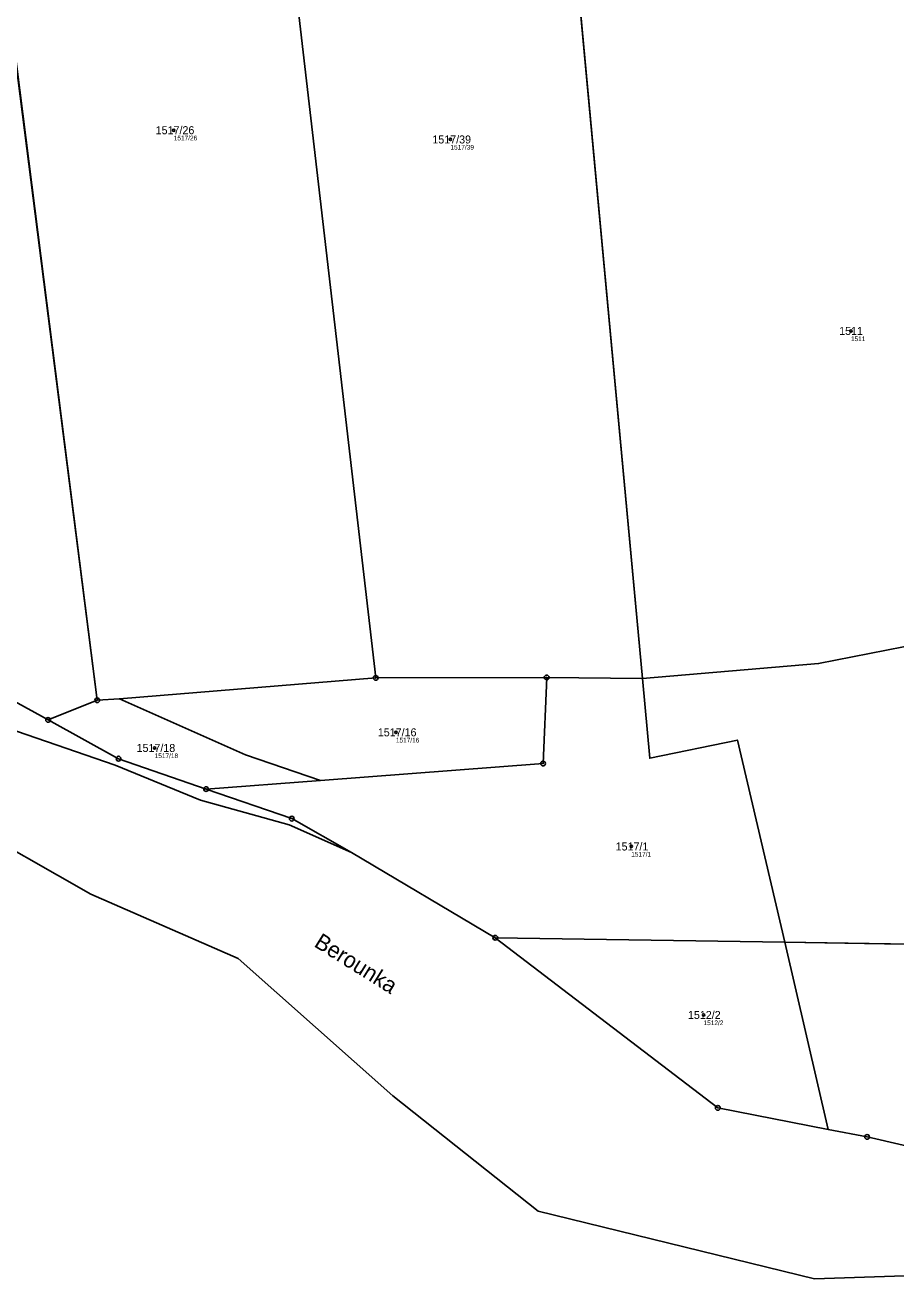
# Model space of a CAD drawing. Extents: x -751550 to -746116, y -1055108 to -1050700.
# Drawn here: x -749512.3 to -749327.2, y -1055107.6 to -1054841.3 of the extents above; entities that cross this region are included whole.
import ezdxf

# ---------------------------------------------------------------- set-up
doc = ezdxf.new("R2010")
doc.units = 0
for name, color, linetype in [('Definiční body', 7, 'Continuous'), ('Hranice parcel', 7, 'Continuous'), ('Parcelní čísla', 7, 'Continuous'), ('Polygon ku', 7, 'Continuous'), ('Polygon parcely', 7, 'Continuous'), ('Pop  PČ popisy', 7, 'Continuous'), ('Značky bodu BP', 7, 'Continuous')]:
    doc.layers.add(name, color=color, linetype=linetype)

msp = doc.modelspace()

# ---------------------------------------------------------------- linework, layer by layer
at = {"layer": 'Definiční body'}
for centre in [(-749480.66, -1054863.59), (-749421.87, -1054865.55), (-749336.76, -1054906.23), (-749433.46, -1054991.49), (-749484.72, -1054994.81), (-749383.45, -1055015.74), (-749368.09, -1055051.53)]:
    msp.add_circle(centre, 0.25, dxfattribs=at)
at = {"layer": 'Hranice parcel'}
for p, q in [((-749396.48, -1054814.13), (-749381.09, -1054980.09)), ((-749496.91, -1054984.67), (-749517.86, -1054820.37)), ((-749437.74, -1054979.93), (-749492.19, -1054984.36)), ((-749437.74, -1054979.93), (-749401.42, -1054979.83)), ((-749381.09, -1054980.09), (-749401.42, -1054979.83)), ((-749507.37, -1054988.85), (-749496.91, -1054984.67)), ((-749492.19, -1054984.36), (-749496.91, -1054984.67)), ((-749449.5, -1055001.7), (-749473.8, -1055003.54)), ((-749442.86, -1055016.99), (-749412.33, -1055035.13)), ((-749412.33, -1055035.13), (-749350.82, -1055036.09)), ((-749412.33, -1055035.13), (-749365.05, -1055071.26)), ((-749256.6, -1055037.55), (-749350.82, -1055036.09)), ((-749350.82, -1055036.09), (-749341.62, -1055075.83)), ((-749365.05, -1055071.26), (-749341.62, -1055075.83)), ((-749341.62, -1055075.83), (-749333.33, -1055077.44))]:
    msp.add_line(p, q, dxfattribs=at)
for points in [[(-749468.76, -1054723.55), (-749454.05, -1054839.07), (-749437.74, -1054979.93)], [(-749827.58, -1054940.21), (-749823.77, -1054939.85), (-749817.22, -1054926.24), (-749806.46, -1054918.15), (-749791.57, -1054918.1), (-749762.12, -1054920.5), (-749754.11, -1054915.08), (-749731.15, -1054909.37), (-749704.18, -1054907.61), (-749694.13, -1054909.07), (-749670.32, -1054916.3), (-749641.24, -1054925.6), (-749607.97, -1054940.21), (-749574.24, -1054956.96), (-749540.13, -1054976.35), (-749522.39, -1054988.44), (-749493.08, -1054998.48), (-749474.96, -1055005.92), (-749456.13, -1055011.14), (-749442.86, -1055016.99)], [(-749565.67, -1054956.49), (-749549.57, -1054965.65), (-749507.37, -1054988.85)], [(-749381.09, -1054980.09), (-749343.63, -1054976.89), (-749300.3, -1054968.35), (-749280.79, -1054962.12)], [(-749401.42, -1054979.83), (-749402.17, -1054998.13), (-749449.5, -1055001.7)], [(-749350.82, -1055036.09), (-749360.9, -1054993.15), (-749379.51, -1054997.01), (-749381.09, -1054980.09)], [(-749492.19, -1054984.36), (-749465.38, -1054996.27), (-749449.5, -1055001.7)], [(-749507.37, -1054988.85), (-749492.39, -1054997.09), (-749473.8, -1055003.54)], [(-749473.8, -1055003.54), (-749455.57, -1055009.83), (-749442.86, -1055016.99)], [(-749526.2, -1055010), (-749498.3, -1055025.9), (-749467, -1055039.5), (-749434.1, -1055068.7), (-749403.2, -1055093.2), (-749344.5, -1055107.6), (-749302.04, -1055106.18), (-749265.75, -1055104.19)], [(-749333.33, -1055077.44), (-749308.55, -1055083.15), (-749254.97, -1055075.95), (-749245.5, -1055072.16)]]:
    msp.add_lwpolyline(points, dxfattribs=at)
at = {"layer": 'Polygon ku'}
msp.add_lwpolyline([(-749526.2, -1055010), (-749498.3, -1055025.9), (-749467, -1055039.5), (-749434.1, -1055068.7), (-749403.2, -1055093.2), (-749344.5, -1055107.6), (-749302.04, -1055106.18), (-749265.75, -1055104.19), (-749247.26, -1055095.19), (-749208.17, -1055076.2), (-749160.88, -1055048.61), (-749145.78, -1055041.61), (-749130.65, -1055034.5), (-749113.89, -1055026.62), (-749080.2, -1055005.63)], dxfattribs=at)
at = {"layer": 'Polygon parcely'}
for points in [[(-749401.42, -1054979.83), (-749381.09, -1054980.09), (-749396.48, -1054814.13), (-749404.53, -1054711.66), (-749437.24, -1054691.62), (-749457.09, -1054684.27), (-749473.81, -1054683.86), (-749468.76, -1054723.55), (-749454.05, -1054839.07), (-749437.74, -1054979.93)], [(-749437.74, -1054979.93), (-749454.05, -1054839.07), (-749468.76, -1054723.55), (-749505.69, -1054730.18), (-749482.46, -1054803.62), (-749514.3, -1054817.1), (-749517.86, -1054820.37), (-749496.91, -1054984.67), (-749492.19, -1054984.36)], [(-749590.08, -1054864.72), (-749588.65, -1054870.79), (-749566.64, -1054952.87), (-749565.67, -1054956.49), (-749549.57, -1054965.65), (-749507.37, -1054988.85), (-749496.91, -1054984.67), (-749517.86, -1054820.37), (-749545.78, -1054844.57), (-749557.43, -1054815.07), (-749565.79, -1054793.94), (-749576.04, -1054766.04), (-749584.86, -1054740.57), (-749586.36, -1054735.92), (-749616.08, -1054754.01), (-749612.17, -1054770.43), (-749601.72, -1054814.99)], [(-749300.3, -1054968.35), (-749280.79, -1054962.12), (-749323.11, -1054829.31), (-749370.31, -1054816.25), (-749381.97, -1054813.02), (-749396.48, -1054814.13), (-749381.09, -1054980.09), (-749343.63, -1054976.89)], [(-749381.09, -1054980.09), (-749379.51, -1054997.01), (-749360.9, -1054993.15), (-749350.82, -1055036.09), (-749256.6, -1055037.55), (-749280.79, -1054962.12), (-749300.3, -1054968.35), (-749343.63, -1054976.89)], [(-749465.38, -1054996.27), (-749449.5, -1055001.7), (-749402.17, -1054998.13), (-749401.42, -1054979.83), (-749437.74, -1054979.93), (-749492.19, -1054984.36)], [(-749442.86, -1055016.99), (-749412.33, -1055035.13), (-749350.82, -1055036.09), (-749360.9, -1054993.15), (-749379.51, -1054997.01), (-749381.09, -1054980.09), (-749401.42, -1054979.83), (-749402.17, -1054998.13), (-749449.5, -1055001.7), (-749473.8, -1055003.54), (-749455.57, -1055009.83)], [(-749507.37, -1054988.85), (-749492.39, -1054997.09), (-749473.8, -1055003.54), (-749449.5, -1055001.7), (-749465.38, -1054996.27), (-749492.19, -1054984.36), (-749496.91, -1054984.67)], [(-749341.62, -1055075.83), (-749350.82, -1055036.09), (-749412.33, -1055035.13), (-749365.05, -1055071.26)], [(-749308.55, -1055083.15), (-749254.97, -1055075.95), (-749245.5, -1055072.16), (-749256.6, -1055037.55), (-749350.82, -1055036.09), (-749341.62, -1055075.83), (-749333.33, -1055077.44)]]:
    msp.add_lwpolyline(points, close=True, dxfattribs=at)
for points in [[(-749522.39, -1054988.44), (-749493.08, -1054998.48), (-749474.96, -1055005.92), (-749456.13, -1055011.14), (-749442.86, -1055016.99), (-749455.57, -1055009.83), (-749473.8, -1055003.54), (-749492.39, -1054997.09), (-749507.37, -1054988.85), (-749549.57, -1054965.65)], [(-749091.02, -1054993), (-749103.98, -1055001.18), (-749166.66, -1055023.96), (-749176.86, -1055030.71), (-749214.93, -1055059.91), (-749245.5, -1055072.16), (-749254.97, -1055075.95), (-749308.55, -1055083.15), (-749333.33, -1055077.44), (-749341.62, -1055075.83), (-749365.05, -1055071.26), (-749412.33, -1055035.13), (-749442.86, -1055016.99), (-749456.13, -1055011.14), (-749474.96, -1055005.92), (-749493.08, -1054998.48), (-749522.39, -1054988.44)], [(-749526.2, -1055010), (-749498.3, -1055025.9), (-749467, -1055039.5), (-749434.1, -1055068.7), (-749403.2, -1055093.2), (-749344.5, -1055107.6), (-749302.04, -1055106.18), (-749265.75, -1055104.19), (-749247.26, -1055095.19), (-749208.17, -1055076.2), (-749160.88, -1055048.61), (-749145.78, -1055041.61), (-749130.65, -1055034.5), (-749113.89, -1055026.62), (-749080.2, -1055005.63)]]:
    msp.add_lwpolyline(points, dxfattribs=at)
at = {"layer": 'Značky bodu BP'}
for centre, radius in [((-749437.74, -1054979.93), 0.5), ((-749401.42, -1054979.83), 0.5), ((-749437.74, -1054979.93), 0.0303), ((-749401.42, -1054979.83), 0.0303), ((-749496.91, -1054984.67), 0.5), ((-749496.91, -1054984.67), 0.0303), ((-749507.37, -1054988.85), 0.5), ((-749507.37, -1054988.85), 0.0303), ((-749492.39, -1054997.09), 0.5), ((-749492.39, -1054997.09), 0.0303), ((-749402.17, -1054998.13), 0.5), ((-749402.17, -1054998.13), 0.0303), ((-749473.8, -1055003.54), 0.5), ((-749473.8, -1055003.54), 0.0303), ((-749455.57, -1055009.83), 0.5), ((-749455.57, -1055009.83), 0.0303), ((-749412.33, -1055035.13), 0.5), ((-749412.33, -1055035.13), 0.0303), ((-749365.05, -1055071.26), 0.5), ((-749365.05, -1055071.26), 0.0303), ((-749333.33, -1055077.44), 0.5), ((-749333.33, -1055077.44), 0.0303)]:
    msp.add_circle(centre, radius, dxfattribs=at)

# ---------------------------------------------------------------- texts
at = {"layer": 'Definiční body'}
for s, p in [('1517/26', (-749480.66, -1054865.75)), ('1517/39', (-749421.87, -1054867.71)), ('1511', (-749336.76, -1054908.39)), ('1517/16', (-749433.46, -1054993.65)), ('1517/18', (-749484.72, -1054996.97)), ('1517/1', (-749383.45, -1055017.9)), ('1512/2', (-749368.09, -1055053.69))]:
    msp.add_text(s, height=1, dxfattribs=at).set_placement(p)
at = {"layer": 'Parcelní čísla'}
for s, p in [('1517/26', (-749484.5, -1054864.44)), ('1517/39', (-749425.71, -1054866.4)), ('1511', (-749339.27, -1054907.08)), ('1517/16', (-749437.3, -1054992.34)), ('1517/18', (-749488.56, -1054995.66)), ('1517/1', (-749386.76, -1055016.59)), ('1512/2', (-749371.4, -1055052.38))]:
    msp.add_text(s, height=1.7, dxfattribs=at).set_placement(p)
at = {"layer": 'Pop  PČ popisy'}
msp.add_text('Berounka', height=3.4, rotation=328, dxfattribs=at).set_placement((-749451.05, -1055036.86))

doc.saveas('drawing.dxf')
